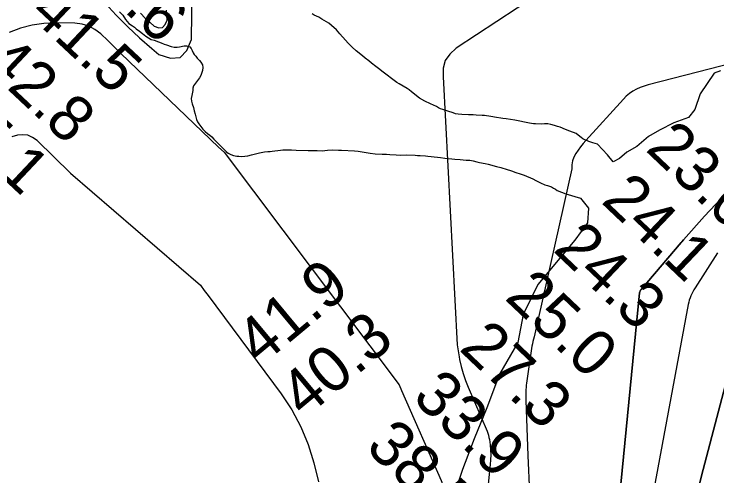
# Model space of a CAD drawing. Extents: x 3146026 to 3183936, y 897894 to 923344.
# Drawn here: x 3177534 to 3178564, y 906736 to 907413 of the extents above; entities that cross this region are included whole.
import ezdxf

# ---------------------------------------------------------------- set-up
doc = ezdxf.new("R2010")
doc.units = 0
for name, color, linetype in [('V-RIVR-RANG', 7, 'Continuous'), ('V-SITE-VEGE', 7, 'Continuous'), ('V-TOPO-DPTH', 7, 'Continuous'), ('V-TOPO-MAJR', 7, 'Continuous'), ('V-TOPO-MINR', 7, 'Continuous'), ('V-TOPO-WATR', 7, 'Continuous')]:
    doc.layers.add(name, color=color, linetype=linetype)

msp = doc.modelspace()

# ---------------------------------------------------------------- linework, layer by layer
at = {"layer": 'V-SITE-VEGE'}
for p, q in [((3177688.9, 907416.9), (3177693.4, 907411.7)), ((3177693.4, 907411.7), (3177697.5, 907405.2)), ((3177973.8, 907412), (3177971, 907413.5)), ((3177980.6, 907409), (3177973.8, 907412)), ((3177697.5, 907405.2), (3177702.6, 907399.4)), ((3177984.9, 907405.9), (3177980.6, 907409)), ((3177995.4, 907399.9), (3177984.9, 907405.9)), ((3177702.6, 907399.4), (3177707.5, 907396)), ((3177707.5, 907396), (3177710.5, 907394.1)), ((3177710.5, 907394.1), (3177713.2, 907391.9)), ((3177713.2, 907391.9), (3177718, 907388.5)), ((3177999.4, 907396.4), (3177995.4, 907399.9)), ((3178006.3, 907390.2), (3177999.4, 907396.4)), ((3177718, 907388.5), (3177722.5, 907384.8)), ((3177722.5, 907384.8), (3177727.1, 907381.2)), ((3177727.1, 907381.2), (3177735.2, 907376.2)), ((3178011.4, 907384.6), (3178006.3, 907390.2)), ((3178019.6, 907375.3), (3178011.4, 907384.6)), ((3177735.2, 907376.2), (3177739.4, 907375)), ((3177739.4, 907375), (3177745.8, 907372.5)), ((3177745.8, 907372.5), (3177749.6, 907371.2)), ((3177749.6, 907371.2), (3177754.3, 907369.4)), ((3178023.7, 907370.8), (3178019.6, 907375.3)), ((3178029.4, 907364.8), (3178023.7, 907370.8)), ((3177754.3, 907369.4), (3177757.7, 907368.3)), ((3177757.7, 907368.3), (3177764.3, 907365.9)), ((3177764.3, 907365.9), (3177768.7, 907365)), ((3177768.7, 907365), (3177773.2, 907364.7)), ((3177773.2, 907364.7), (3177776.6, 907365.2)), ((3177776.6, 907365.2), (3177783.3, 907366.8)), ((3177783.3, 907366.8), (3177786.9, 907366.8)), ((3177786.9, 907366.8), (3177791.7, 907365.2)), ((3177791.7, 907365.2), (3177793.6, 907362.7)), ((3177793.6, 907362.7), (3177795, 907359.9)), ((3177795, 907359.9), (3177796.5, 907356.8)), ((3178035.5, 907359.6), (3178029.4, 907364.8)), ((3177796.5, 907356.8), (3177798.1, 907354.2)), ((3177798.1, 907354.2), (3177800.4, 907351.9)), ((3177800.4, 907351.9), (3177802.6, 907349)), ((3178044.5, 907352.3), (3178035.5, 907359.6)), ((3178048.7, 907349), (3178044.5, 907352.3)), ((3177802.6, 907349), (3177805.9, 907345.5)), ((3177805.9, 907345.5), (3177808, 907343)), ((3177808, 907343), (3177810.4, 907339.1)), ((3177810.4, 907339.1), (3177810.8, 907334.9)), ((3178054, 907344.8), (3178048.7, 907349)), ((3178057.8, 907341.5), (3178054, 907344.8)), ((3178064.1, 907336.7), (3178057.8, 907341.5)), ((3177810.5, 907330.5), (3177807.7, 907323.3)), ((3177810.8, 907334.9), (3177810.5, 907330.5)), ((3178069.8, 907332.1), (3178064.1, 907336.7)), ((3178073.1, 907329.6), (3178069.8, 907332.1)), ((3178095.1, 907313.3), (3178073.1, 907329.6)), ((3178568.9, 907330.1), (3178559.9, 907326.8)), ((3177806, 907320.1), (3177797.3, 907308.3)), ((3177807.7, 907323.3), (3177806, 907320.1)), ((3178559.9, 907326.8), (3178539.3, 907296.3)), ((3177797.3, 907308.3), (3177796.2, 907304.7)), ((3178098.3, 907311.2), (3178095.1, 907313.3)), ((3178110, 907304.5), (3178098.3, 907311.2)), ((3177795.9, 907301.5), (3177794.5, 907293.8)), ((3177796.2, 907304.7), (3177795.9, 907301.5)), ((3178112.9, 907302.4), (3178110, 907304.5)), ((3178116.3, 907299.5), (3178112.9, 907302.4)), ((3178128.3, 907290.3), (3178116.3, 907299.5)), ((3177794.5, 907293.8), (3177793.9, 907289.4)), ((3177793.9, 907289.4), (3177794.2, 907285.6)), ((3178136.1, 907285.9), (3178128.3, 907290.3)), ((3178539.3, 907296.3), (3178531.3, 907273.7)), ((3177794.2, 907285.6), (3177795.3, 907281.7)), ((3177795.3, 907281.7), (3177797, 907276.5)), ((3178144.2, 907281.8), (3178136.1, 907285.9)), ((3178152.8, 907277.8), (3178144.2, 907281.8)), ((3178155.9, 907276.1), (3178152.8, 907277.8)), ((3177797, 907276.5), (3177798.1, 907271.6)), ((3177798.1, 907271.6), (3177799.4, 907266.9)), ((3178158.9, 907274.6), (3178155.9, 907276.1)), ((3178162.3, 907273.3), (3178158.9, 907274.6)), ((3178169.5, 907271.1), (3178162.3, 907273.3)), ((3178177.3, 907268.5), (3178169.5, 907271.1)), ((3178180.9, 907267.4), (3178177.3, 907268.5)), ((3178184.5, 907266.7), (3178180.9, 907267.4)), ((3178531.3, 907273.7), (3178522, 907261.8)), ((3177799.4, 907266.9), (3177801.4, 907259)), ((3177801.4, 907259), (3177802.9, 907255.6)), ((3178190.1, 907266.1), (3178184.5, 907266.7)), ((3178200, 907265.9), (3178190.1, 907266.1)), ((3178206.8, 907265.7), (3178200, 907265.9)), ((3178211.2, 907265.2), (3178206.8, 907265.7)), ((3178219.7, 907264.9), (3178211.2, 907265.2)), ((3178223.5, 907264.6), (3178219.7, 907264.9)), ((3178232.5, 907263.4), (3178223.5, 907264.6)), ((3178240.8, 907261.8), (3178232.5, 907263.4)), ((3178247, 907260.8), (3178240.8, 907261.8)), ((3178250, 907260.5), (3178247, 907260.8)), ((3178254.8, 907259.6), (3178250, 907260.5)), ((3178267.9, 907257.8), (3178254.8, 907259.6)), ((3178289.3, 907253.5), (3178267.9, 907257.8)), ((3178522, 907261.8), (3178500.7, 907253.8)), ((3177802.9, 907255.6), (3177804.7, 907252.5)), ((3177804.7, 907252.5), (3177810.7, 907244.9)), ((3178294.9, 907252.7), (3178289.3, 907253.5)), ((3178298.1, 907252.4), (3178294.9, 907252.7)), ((3178307.4, 907252.2), (3178298.1, 907252.4)), ((3178311.2, 907252.3), (3178307.4, 907252.2)), ((3178316.3, 907252.3), (3178311.2, 907252.3)), ((3178320.5, 907251.4), (3178316.3, 907252.3)), ((3178325.7, 907250.1), (3178320.5, 907251.4)), ((3178330.3, 907248.7), (3178325.7, 907250.1)), ((3178333.9, 907247.8), (3178330.3, 907248.7)), ((3178341.8, 907244.2), (3178333.9, 907247.8)), ((3178500.7, 907253.8), (3178479.5, 907243.1)), ((3177810.7, 907244.9), (3177814.4, 907241.1)), ((3177814.4, 907241.1), (3177817.8, 907238.2)), ((3177817.8, 907238.2), (3177821.1, 907235.7)), ((3178348.4, 907242), (3178341.8, 907244.2)), ((3178357.4, 907238.2), (3178348.4, 907242)), ((3178360.7, 907236.1), (3178357.4, 907238.2)), ((3178364.9, 907232.6), (3178360.7, 907236.1)), ((3178479.5, 907243.1), (3178463.5, 907233.8)), ((3177821.1, 907235.7), (3177823.7, 907233.4)), ((3177823.7, 907233.4), (3177827, 907230.1)), ((3177827, 907230.1), (3177830, 907227.2)), ((3177830, 907227.2), (3177836.4, 907220.4)), ((3178367.4, 907230.6), (3178364.9, 907232.6)), ((3178370.2, 907228.9), (3178367.4, 907230.6)), ((3178373, 907227.9), (3178370.2, 907228.9)), ((3178376.2, 907226.6), (3178373, 907227.9)), ((3178379.1, 907225.5), (3178376.2, 907226.6)), ((3178463.5, 907233.8), (3178446.2, 907219.2)), ((3177836.4, 907220.4), (3177841.9, 907214.8)), ((3178382.1, 907224.8), (3178379.1, 907225.5)), ((3178385.2, 907223.5), (3178382.1, 907224.8)), ((3178388.6, 907222.5), (3178385.2, 907223.5)), ((3178403.7, 907207.2), (3178388.6, 907222.5)), ((3178446.2, 907219.2), (3178431.6, 907211.2)), ((3177841.9, 907214.8), (3177845.3, 907211.7)), ((3177845.3, 907211.7), (3177848, 907209.5)), ((3177848, 907209.5), (3177851.8, 907207.5)), ((3177851.8, 907207.5), (3177855.8, 907206)), ((3177855.8, 907206), (3177860.4, 907205.3)), ((3177860.4, 907205.3), (3177863.4, 907205)), ((3177872.3, 907205), (3177876.9, 907205.7)), ((3177876.9, 907205.7), (3177882.2, 907206.9)), ((3177882.2, 907206.9), (3177893.8, 907210.1)), ((3177893.8, 907210.1), (3177901.1, 907211.7)), ((3177901.1, 907211.7), (3177905.9, 907211.8)), ((3177905.9, 907211.8), (3177909.3, 907212.1)), ((3177909.3, 907212.1), (3177912.4, 907212.6)), ((3177912.4, 907212.6), (3177924.3, 907213.9)), ((3177924.3, 907213.9), (3177927.9, 907214.2)), ((3177927.9, 907214.2), (3177940.8, 907214.5)), ((3177940.8, 907214.5), (3177947.7, 907213.9)), ((3177947.7, 907213.9), (3177965, 907213.2)), ((3177965, 907213.2), (3177968.6, 907213.2)), ((3177968.6, 907213.2), (3177971.7, 907213.2)), ((3177971.7, 907213.2), (3177978, 907213.2)), ((3177978, 907213.2), (3177985.7, 907212.9)), ((3177985.7, 907212.9), (3177993.4, 907213.7)), ((3177993.4, 907213.7), (3178000.4, 907214.2)), ((3178000.4, 907214.2), (3178009.5, 907214.1)), ((3178009.5, 907214.1), (3178014.1, 907213.7)), ((3178014.1, 907213.7), (3178033.1, 907212.8)), ((3178033.1, 907212.8), (3178038.1, 907212.4)), ((3178038.1, 907212.4), (3178047.1, 907211)), ((3178047.1, 907211), (3178056, 907209.6)), ((3178056, 907209.6), (3178063, 907208.7)), ((3178063, 907208.7), (3178073.5, 907208.1)), ((3178073.5, 907208.1), (3178079.6, 907208)), ((3178079.6, 907208), (3178084.7, 907207.7)), ((3178084.7, 907207.7), (3178094.1, 907207)), ((3178094.1, 907207), (3178100.5, 907206.8)), ((3178100.5, 907206.8), (3178109, 907206.9)), ((3178109, 907206.9), (3178121.6, 907206.5)), ((3178121.6, 907206.5), (3178125.2, 907206.2)), ((3178125.2, 907206.2), (3178129.1, 907206.3)), ((3178129.1, 907206.3), (3178137.1, 907205.6)), ((3178137.1, 907205.6), (3178140.1, 907205.2)), ((3178411.7, 907196.6), (3178403.7, 907207.2)), ((3178431.6, 907211.2), (3178421, 907201.9)), ((3177863.4, 907205), (3177868.1, 907204.7)), ((3177868.1, 907204.7), (3177872.3, 907205)), ((3178140.1, 907205.2), (3178154.5, 907203.7)), ((3178154.5, 907203.7), (3178158.9, 907203.3)), ((3178158.9, 907203.3), (3178165.4, 907202.3)), ((3178165.4, 907202.3), (3178175.6, 907201.1)), ((3178175.6, 907201.1), (3178179.9, 907200.6)), ((3178179.9, 907200.6), (3178187.6, 907200.2)), ((3178187.6, 907200.2), (3178196.5, 907199.4)), ((3178196.5, 907199.4), (3178202, 907199.2)), ((3178202, 907199.2), (3178206.6, 907198.5)), ((3178206.6, 907198.5), (3178212, 907196.8)), ((3178212, 907196.8), (3178215.9, 907195.8)), ((3178215.9, 907195.8), (3178224.4, 907194.2)), ((3178421, 907201.9), (3178411.7, 907196.6)), ((3178224.4, 907194.2), (3178228.7, 907193.2)), ((3178228.7, 907193.2), (3178240.9, 907190.2)), ((3178240.9, 907190.2), (3178247, 907188.4)), ((3178247, 907188.4), (3178250.2, 907187.6)), ((3178250.2, 907187.6), (3178253.6, 907186.5)), ((3178253.6, 907186.5), (3178264.4, 907183.3)), ((3178264.4, 907183.3), (3178267.6, 907181.8)), ((3178267.6, 907181.8), (3178270.5, 907180.5)), ((3178270.5, 907180.5), (3178274, 907179.5)), ((3178274, 907179.5), (3178277, 907178.9)), ((3178277, 907178.9), (3178281.5, 907177.3)), ((3178281.5, 907177.3), (3178294.1, 907171.8)), ((3178294.1, 907171.8), (3178298.3, 907169.6)), ((3178298.3, 907169.6), (3178301.2, 907168.2)), ((3178301.2, 907168.2), (3178305.5, 907165.8)), ((3178305.5, 907165.8), (3178311.9, 907163.3)), ((3178311.9, 907163.3), (3178315.5, 907162.3)), ((3178315.5, 907162.3), (3178318.5, 907161.3)), ((3178318.5, 907161.3), (3178321.4, 907160.1)), ((3178321.4, 907160.1), (3178324.6, 907158.4)), ((3178324.6, 907158.4), (3178327.3, 907156.7)), ((3178327.3, 907156.7), (3178329.9, 907154.8)), ((3178329.9, 907154.8), (3178342.5, 907150)), ((3178342.5, 907150), (3178363.8, 907143.4)), ((3178363.8, 907143.4), (3178375.8, 907128.8)), ((3178375.8, 907128.8), (3178374.4, 907107.5)), ((3178374.4, 907107.5), (3178355.8, 907082.2)), ((3178355.8, 907082.2), (3178301.3, 907017.1)), ((3178301.3, 907017.1), (3178280, 906973.2)), ((3178280, 906973.2), (3178272.1, 906931.9)), ((3178272.1, 906931.9), (3178245.5, 906885.4)), ((3178245.5, 906885.4), (3178226.9, 906836.2)), ((3178226.9, 906836.2), (3178208.3, 906791)), ((3178208.3, 906791), (3178191, 906745.8)), ((3178191, 906745.8), (3178177.7, 906705.9))]:
    msp.add_line(p, q, dxfattribs=at)
at = {"layer": 'V-TOPO-DPTH'}
for points in [[(3177758.4, 906034.5), (3177923.1, 906118.6), (3178070.8, 906208.3), (3178296.4, 906350.5), (3178360.1, 906400), (3178394.8, 906441.7), (3178395.5, 906443.9), (3178450.3, 907004.8), (3178451.8, 907008.7), (3178452.7, 907009.8), (3178511.5, 907078.6), (3178512.3, 907079.6), (3178514.8, 907082.7), (3178545.4, 907117.2), (3178561.7, 907134.3), (3178578.7, 907150.6)], [(3178625.5, 907058.1), (3178541.2, 906736.7), (3178528.3, 906684.7), (3178513.7, 906633.2), (3178496.5, 906582.5), (3178477.5, 906532.4), (3178440, 906440.5), (3178438.3, 906436.8), (3178436.5, 906433.2), (3178434.4, 906429.8), (3178369.1, 906359.5), (3178287.2, 906293.9), (3178122.2, 906169.8), (3177941.1, 906045.8), (3177869.3, 906010.5), (3177823.3, 905991.5)], [(3177823.3, 905991.5), (3177869.3, 906010.5), (3177941.1, 906045.8), (3178122.2, 906169.8), (3178287.2, 906293.9), (3178369.1, 906359.5), (3178434.4, 906429.8), (3178436.5, 906433.2), (3178438.3, 906436.8), (3178440, 906440.5), (3178477.5, 906532.4), (3178496.5, 906582.5), (3178513.7, 906633.2), (3178528.3, 906684.7), (3178541.2, 906736.7), (3178625.5, 907058.1)]]:
    msp.add_lwpolyline(points, dxfattribs=at)
at = {"layer": 'V-TOPO-MAJR'}
for points in [[(3177833.7, 907218.2), (3177690.6, 907355.6), (3177683.8, 907362.5), (3177676.9, 907369.4), (3177670, 907376.2), (3177663, 907382.9), (3177661.2, 907384.6), (3177652.8, 907390.9), (3177643.8, 907395.8), (3177633.9, 907398.6), (3177623.4, 907400), (3177595.7, 907400.5), (3177578, 907399.6), (3177560.7, 907397.2), (3177543.8, 907392.6), (3177527.2, 907386.5)], [(3177833.7, 907218.2), (3177841.8, 907211), (3178098.2, 906869.9), (3178101.7, 906861.8), (3178159.9, 906729.7), (3178160.8, 906727.3), (3178161.4, 906724.8), (3178161.8, 906722.3), (3178161.9, 906719.7), (3178161.7, 906717.1), (3178161.3, 906714.6), (3178160.6, 906712.1), (3178101.3, 906534.2), (3178089.2, 906514.4), (3178079.6, 906500.8), (3177865.2, 906262.9), (3177713.7, 906132.5), (3177664.5, 906096.6)]]:
    msp.add_lwpolyline(points, dxfattribs=at)
at = {"layer": 'V-TOPO-MINR'}
for points in [[(3177667.7, 907429.4), (3177683.9, 907411.8), (3177700.7, 907394.7), (3177718.2, 907378.4), (3177736.2, 907362.7), (3177746.5, 907354), (3177763.4, 907348.9), (3177777.4, 907349.9), (3177787.3, 907360), (3177794.3, 907376.1), (3177795.4, 907488.4)], [(3178330.8, 907461.5), (3178181.9, 907363.2), (3178172.5, 907354.8), (3178165.8, 907345.3), (3178162.9, 907333.9), (3178162.7, 907321.4), (3178183.4, 906928.5), (3178184.5, 906919.6), (3178186, 906910.8), (3178186.7, 906907.3), (3178189.2, 906896.9), (3178192.2, 906886.6), (3178195.7, 906876.5), (3178199.6, 906866.5), (3178227, 906802.2), (3178228.1, 906799.2), (3178229.1, 906796.1), (3178229.8, 906793), (3178230.4, 906789.8), (3178231.4, 906781.8), (3178232.1, 906774.6), (3178232.5, 906767.4), (3178232.3, 906760.2), (3178231.8, 906753), (3178224.8, 906685.8)], [(3177719.3, 907414.6), (3177726.2, 907407.6), (3177733.4, 907400.8), (3177739.3, 907395.5), (3177746.2, 907393.4), (3177751.9, 907393.7), (3177755.7, 907398), (3177758.3, 907404.7), (3177757.4, 907419.2)], [(3178624.7, 907351.3), (3178462.9, 907309.6), (3178457.1, 907307.9), (3178451.4, 907305.8), (3178445.9, 907303.2), (3178440.6, 907300.3), (3178435.6, 907296.8), (3178430.9, 907293), (3178426.8, 907288.7), (3178371.9, 907228), (3178367.8, 907223.5), (3178363.9, 907218.8), (3178360.4, 907213.9), (3178357, 907208.9), (3178354.3, 907203.6), (3178352.4, 907198.1), (3178351.4, 907192.4), (3178351.1, 907186.5), (3178295.9, 906940.1), (3178294.9, 906936.8), (3178294.1, 906933.5), (3178293.4, 906930.1), (3178292.8, 906926.7), (3178284.9, 906872.6), (3178284.5, 906869.4), (3178284.1, 906866.2), (3178283.9, 906863), (3178283.8, 906859.8), (3178283.8, 906856.6), (3178283.8, 906853.4), (3178283.8, 906850.2), (3178283.9, 906847), (3178287, 906766.3), (3178289.4, 906711.6)], [(3177617.1, 907180.1), (3177567.9, 907228), (3177561.5, 907232.6), (3177554.6, 907235.7), (3177547.1, 907236.5), (3177539.2, 907236), (3177531.1, 907233.5)], [(3177617.1, 907180.1), (3177807.2, 907016), (3177812.8, 907008.3), (3177818.4, 907000.7), (3177925.5, 906856.6), (3177940.9, 906833.1), (3177954.4, 906808.5), (3177965, 906782.6), (3177973.5, 906755.7), (3177980, 906728)], [(3178578.7, 907150.6), (3178561.7, 907134.3), (3178545.4, 907117.2), (3178514.8, 907082.7), (3178512.3, 907079.6), (3178511.5, 907078.6), (3178452.7, 907009.8), (3178451.8, 907008.7), (3178450.3, 907004.8), (3178395.5, 906443.9), (3178394.8, 906441.7), (3178360.1, 906400), (3178296.4, 906350.5), (3178070.8, 906208.3), (3177923.1, 906118.6), (3177758.4, 906034.5)], [(3178564.5, 907063.5), (3178531.7, 907012.2), (3178530, 907009.3), (3178528.4, 907006.4), (3178526.9, 907003.4), (3178525.5, 907000.4), (3178524.3, 906997.3), (3178523.3, 906994.2), (3178522.4, 906991), (3178521.7, 906987.7), (3178460.6, 906658.8)]]:
    msp.add_lwpolyline(points, dxfattribs=at)
at = {"layer": 'V-TOPO-WATR'}
msp.add_lwpolyline([(3178625.5, 907058.1), (3178541.2, 906736.7), (3178528.3, 906684.7), (3178513.7, 906633.2), (3178496.5, 906582.5), (3178477.5, 906532.4), (3178440, 906440.5), (3178438.3, 906436.8), (3178436.5, 906433.2), (3178434.4, 906429.8), (3178369.1, 906359.5), (3178287.2, 906293.9), (3178122.2, 906169.8), (3177941.1, 906045.8), (3177869.3, 906010.5), (3177823.3, 905991.5)], dxfattribs=at)

# ---------------------------------------------------------------- texts
at = {"layer": 'V-RIVR-RANG'}
for s, rotation, p in [('24.6', 316.7683, (3177621.3, 907486.6)), ('41.5', 316.7683, (3177554.4, 907412.3)), ('42.8', 316.7683, (3177486.1, 907339.2)), ('45.1', 316.7683, (3177419.5, 907264.6)), ('23.0', 316.4183, (3178457.7, 907214.1)), ('24.1', 316.4183, (3178392.7, 907137.9)), ('24.3', 316.4183, (3178322.3, 907066.9)), ('41.9', 39.7783, (3177895.1, 906896.1)), ('25.0', 316.4183, (3178251.4, 906996.3)), ('40.3', 39.7783, (3177959.5, 906819.6)), ('27.3', 316.4183, (3178184.7, 906921.7)), ('33.9', 316.4183, (3178115.8, 906849.3)), ('38.5', 316.4183, (3178047.2, 906776.5))]:
    msp.add_text(s, height=67, rotation=rotation, dxfattribs=at).set_placement(p)

doc.saveas('drawing.dxf')
